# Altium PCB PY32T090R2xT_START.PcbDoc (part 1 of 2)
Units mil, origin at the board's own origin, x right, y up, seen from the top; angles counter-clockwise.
Board outline 1771.65 x 3866.06 mil, 2 copper layers (Top Layer, Bottom Layer), stack 21 mil thick; 137 components, 162 nets, 557 pads, 319 vias.
Unrouted connection lines stored in the file: 5.
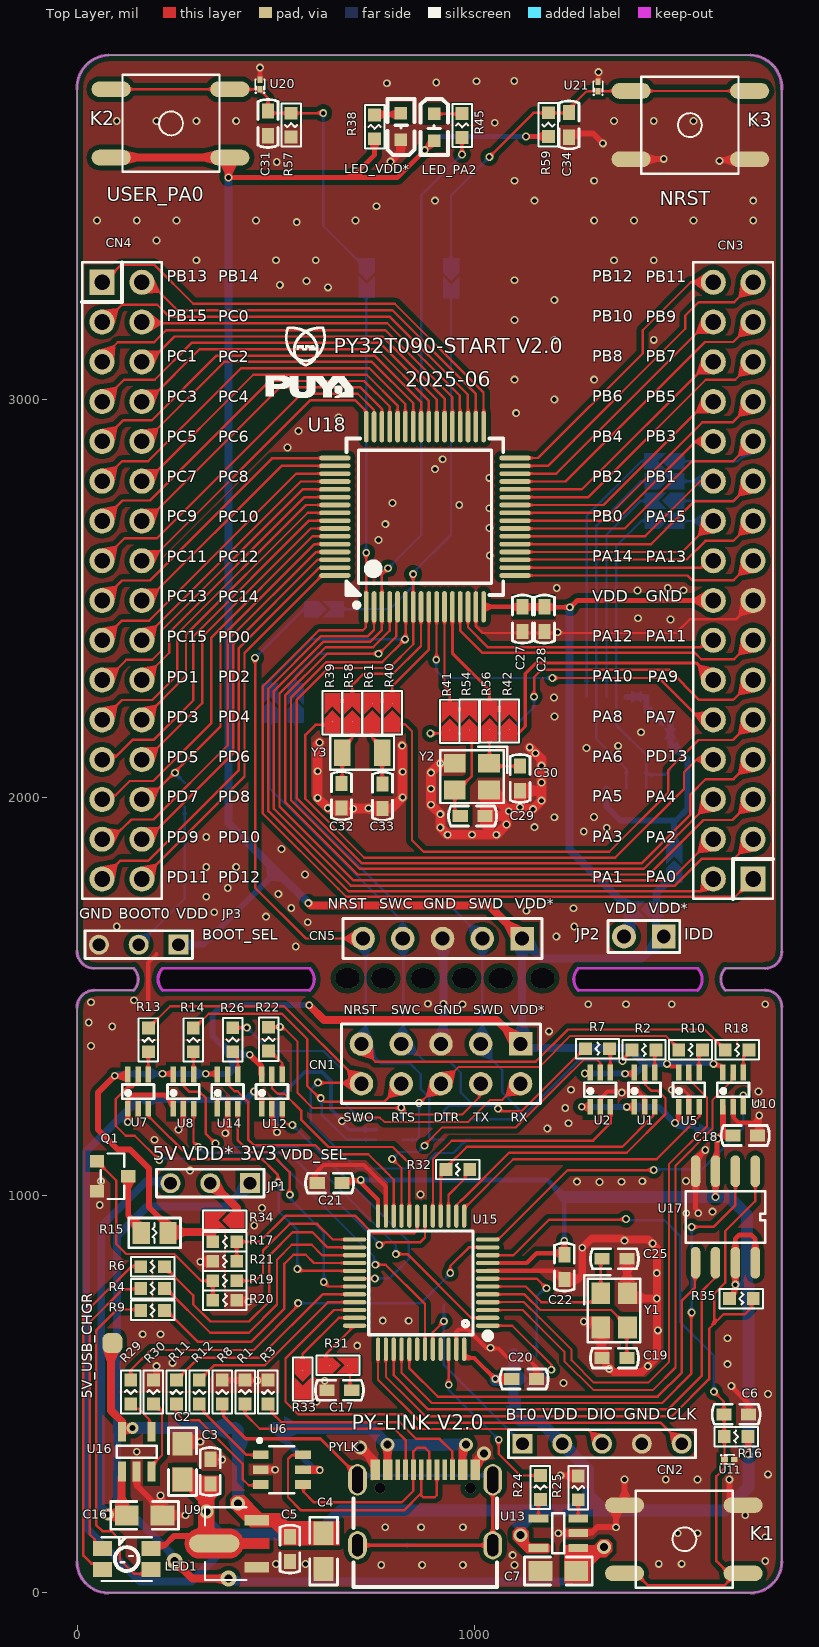
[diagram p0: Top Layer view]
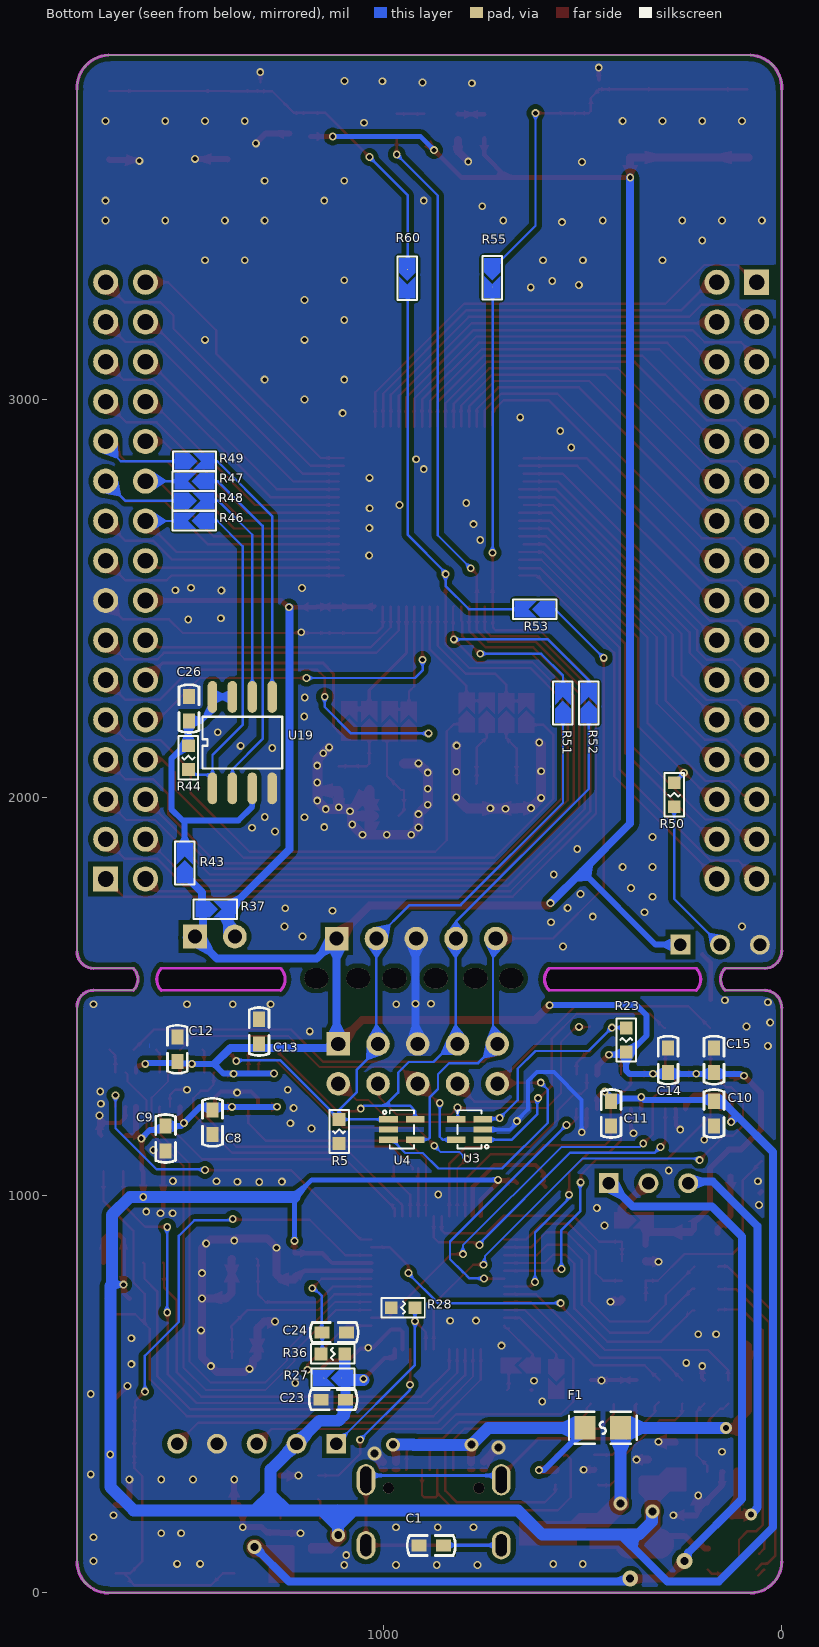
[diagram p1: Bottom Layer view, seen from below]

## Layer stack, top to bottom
Top Solder: solder mask 0.4, Solder Resist, Dk 3.5
Top Layer: signal copper 1.4
Dielectric 2: prepreg 2.8, Composite dielectric, Dk 4.1
Dielectric 1: prepreg 12.6, Composite dielectric, Dk 4.1
Dielectric 3: prepreg 2.8, Composite dielectric, Dk 4.1
Bottom Layer: signal copper 1.4
Bottom Solder: solder mask 0.4, Solder Resist, Dk 3.5

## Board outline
0,78.74 0,1470 cw(c43.75,1471.25) 42.5,1515 142.5,1515 ccw(c115,1542.5) 142.5,1570 42.5,1570 cw(c43.75,1613.75) 0,1615 0,3779.53 cw(c82.64,3783.42) 78.74,3866.06 1692.91,3866.06 cw(c1689.02,3783.43) 1771.65,3779.53 1771.65,1611.65 cw(c1730,1611.65) 1730,1570 1630,1570 ccw(c1657.5,1542.5) 1630,1515 1730,1515 cw(c1730,1473.35) 1771.65,1473.35 1771.65,78.74 cw(c1692.91,78.74) 1692.91,0 78.74,0 cw(c78.74,78.74)
cut-out: 215,1515 cw(c242.5,1542.5) 215,1570 585,1570 cw(c557.5,1542.5) 585,1515 565,1515
cut-out: 1260,1515 cw(c1287.5,1542.5) 1260,1570 1560,1570 cw(c1532.5,1542.5) 1560,1515

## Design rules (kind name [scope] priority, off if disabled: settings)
Clearance polygon [InPolygon] p1: gap=12 ignorepadtopadclearanceinfootprint=TRUE
Clearance [All] p2: gap=8 ignorepadtopadclearanceinfootprint=TRUE
HoleToHoleClearance [All] p1: gap=1 allowstackedmicrovias=TRUE
MinimumSolderMaskSliver [All] p1: minsoldermaskwidth=0
PlaneClearance [All] p1: clearance=8
PlaneConnect [All] p1: planeconnectstyle=Direct reliefexpansion=20 reliefentries=4 reliefconductorwidth=10 reliefairgap=10
PolygonConnect [All] p1: connectstyle=Direct reliefconductorwidth=10 reliefentries=4 polygonreliefangle="90 Angle" airgapwidth=10
RoutingVias [All] p1: holewidth=28 width=50 viastyle="Through Hole" minholewidth=28 minwidth=50 maxholewidth=28 maxwidth=50
SilkToSilkClearance [All] p1: silktosilkclearance=0
SilkToSolderMaskClearance [IsPad] p1: minsilkscreentomaskgap=0 clearancetoexposedcopper=TRUE
SolderMaskExpansion [All] p1: expansion=4 istentingtop=FALSE
UnRoutedNet [All] p1: checkbadconnections=TRUE
Width [All] p1: maxlimit=100 minlimit=5 preferedwidth=8
23 further rules are at their usual default settings.

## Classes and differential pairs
component class PY32T090R2xT_START: 3 C26 C27 C28 C29 C30 C31 C32 C33 C34 CN3 CN4 CN5 JP2 JP3 K2 K3 LED_PA2 LED_VDD* R37 R38 R39 R40 R41 R42 R43 R44 R45 R46 R47 R48 R49 R50 R51 R52 R53 R54 R55 R56 R57 R58 R59 R60 R61 U18 U19 U20 U21 Y2 Y3
component class PY32F403C1xT_LINK: 5V_USB_CHGR C1 C2 C3 C4 C5 C6 C7 C8 C9 C10 C11 C12 C13 C14 C15 C16 C17 C18 C19 C20 C21 C22 C23 C24 C25 CN1 CN2 F1 JP1 K1 LED1 PYLK Q1 R1 R2 R3 R4 R5 R6 R7 R8 R9 R10 R11 R12 R13 R14 R15 R16 R17 R18 R19 R20 R21 R22 R23 R24 R25 R26 R27 R28 R29 R30 R31 R32 R33 R34 R35 R36 U1 U2 U3 U4 U5 U6 U7 U8 U9 U10 U11 U12 U13 U14 U15 U16 U17 Y1

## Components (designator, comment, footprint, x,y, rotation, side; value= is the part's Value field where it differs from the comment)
5V_USB_CHGR "TP_SIN" TP_SIN 89.02,627.93 r90 top
C1 "4.7nF" C0603 881,119 r180 bottom
C2 "10uF" C0805 265,330 r270 top
C3 "100nF" C0603 335,305 r270 top
C4 "10uF" C0805 620,105 r90 top
C5 "100nF" C0603 535,110 r90 top
C6 "100nF" C0603 1657,449 r180 top
C7 "10uF" C0805 1210,55 r0 top
C8 "100nF" C0603 1431,1183 r90 bottom value=104
C9 "100nF" C0603 1548.9,1142.3 r90 bottom value=104
C10 "100nF" C0603 170.2,1204.9 r90 bottom value=104
C11 "100nF" C0603 429,1204.9 r90 bottom value=104
C12 "100nF" C0603 1519.4,1366.6 r270 bottom value=104
C13 "100nF" C0603 1313.8,1411.1 r270 bottom value=104
C14 "100nF" C0603 285.5,1339.2 r270 bottom value=104
C15 "100nF" C0603 170.5,1339.2 r270 bottom value=104
C16 "10uF" C0805 170,195 r180 top
C17 "100nF" C0603 659.59,509.5 r0 top
C18 "100nF" C0603 1680,1150 r180 top value=104
C19 "22pF" C0603 1351.12,590 r0 top
C20 "100nF" C0603 1123.87,537.59 r180 top value=104
C21 "100nF" C0603 635,1030 r0 top value=104
C22 "100nF" C0603 1225.12,819 r90 top value=104
C23 "100nF" C0603 1127.74,485.58 r180 bottom value=104
C24 "100nF" C0603 1125.12,655 r0 bottom value=104
C25 "22pF" C0603 1351.12,840 r180 top
C26 "100nF" C0603 1490.07,2222.92 r270 bottom value=104
C27 "100nF" C0603 1120,2448 r90 top value=104
C28 "1uF" C0603 1175,2448 r90 top
C29 "22pF" C0603 994.4,1953.04 r180 top
C30 "22pF" C0603 1113.83,2047.37 r90 top
C31 "100nF" C0603 480,3694 r90 top
C32 "22pF" C0603 664.8,2003.88 r90 top
C33 "22pF" C0603 767.97,2002.87 r90 top
C34 "100nF" C0603 1237,3690.5 r90 top
CN1 "2X5P" HDR2X5 1115,1380 r180 top
CN2 "CON5" CON5 1120,375 r0 top
CN3 "2X16P 2.54mm" HDR-TH_32P-P2.54-V-M-R2-C16-S2.54-3 1649.59,2544.77 r90 top
CN4 "2X16P 2.54mm" HDR-TH_32P-P2.54-V-M-R2-C16-S2.54-3 113.04,2544.77 r270 top
CN5 "Header 5" HDR1X5 1118.94,1645 r180 top
F1 "JK-SMD0805-050-16V" F0805 450,415 r180 bottom
JP1 "CON3" CON3 435,1030 r180 top
JP2 "CON2" CON2 1475,1650 r180 top
JP3 "CON3" CON3 255,1629.56 r180 top
K1 "TS-KG02S-AT43F" SW-SMD_4P-L6.0-W6.0-P4.50-LS8.5 1527.55,134.7 r180 top
K2 "TS-KG02S-AT43F" SW-SMD_4P-L6.0-W6.0-P4.50-LS8.5 237,3694 r180 top
K3 "TS-KG02S-AT43F" SW-SMD_4P-L6.0-W6.0-P4.50-LS8.5 1540,3690 r0 top
LED1 "MHPA3528RGBCT" LED-ARRAY-SMD_4P-L3.5-W2.8-TL 125,85 r0 top
LED_PA2 "GREEN" 0603_LED 897,3670 r270 top
LED_VDD* "RED" 0603_LED 815,3701 r90 top
PYLK "KH-TYPE-C-16P" USB-C-SMD_KH-TYPE-C-16P 875.2,214.81 r0 top locked
Q1 "2302" SOT23 89.37,1047.4 r90 top value=SI2302
R1 "5.1K" R0603 422.49,504.99 r270 top
R2 "27R" R0603 1425.21,1365 r180 top
R3 "5.1K" R0603 480,505 r90 top
R4 "680R" R0603 190,765 r0 top
R5 "1M" R0603 1113,1160 r90 bottom
R6 "680R" R0603 190,820 r0 top
R7 "27R" R0603 1308.39,1368.1 r180 top
R8 "1M" R0603 365,505 r90 top
R9 "680R" R0603 190,710 r0 top
R10 "27R" R0603 1542.35,1365 r180 top
R11 "27R" R0603 250,505 r90 top
R12 "27R" R0603 307.5,505 r90 top
R13 "27R" R0603 179.66,1390.08 r90 top
R14 "27R" R0603 292.3,1390.1 r90 top
R15 "100R" R0805 195,905 r0 top
R16 "10K" R0603 1657,393 r0 top
R17 "20K" R0603 371.52,882.61 r180 top
R18 "27R" R0603 1659.49,1365 r180 top
R19 "100R" R0603 371.53,784.78 r0 top
R20 "100K" R0603 371.52,735.88 r180 top
R21 "10K" R0603 371.53,833.69 r0 top
R22 "27R" R0603 481.63,1392.11 r90 top
R23 "4.7K" R0603 391,1390 r270 bottom
R24 "4.7K" R0603 1165,265 r270 top
R25 "16K" R0603 1260,264 r270 top
R26 "27R" R0603 391.2,1390.7 r90 top
R27 "0R" JP2_SMD 1128,540 r180 bottom
R28 "10K" R0603 952,717.08 r0 bottom
R29 "4.7K" R0603 135,505 r270 top
R30 "16K" R0603 192,505 r270 top
R31 "0R" JP2_SMD 656.21,571.75 r180 top
R32 "680R" R0603 957.46,1064.37 r0 top
R33 "0R" JP2_SMD 566.96,537.4 r90 top
R34 "0R" JP2_SMD 371,937 r0 top
R35 "100K" R0603 1670,740 r180 top
R36 "10K" R0603 1128.6,600.62 r180 bottom
R37 "0R" JP2_SMD 1423.75,1718.35 r0 bottom
R38 "680R" R0603 748,3685.5 r270 top
R39 "0R" JP2_SMD 642.19,2212.17 r270 top
R40 "0R" JP2_SMD 792,2213 r270 top
R41 "0R" JP2_SMD 937.26,2190.77 r270 top
R42 "0R" JP2_SMD 1087,2192 r270 top
R43 "0R/NC" JP2_SMD 1501,1835 r270 bottom
R44 "100K" R0603 1491.66,2099.84 r90 bottom
R45 "680R" R0603 968,3689 r270 top
R46 "0R/NC" JP2_SMD 1477,2695.26 r180 bottom
R47 "0R/NC" JP2_SMD 1476.59,2794.33 r180 bottom
R48 "0R/NC" JP2_SMD 1477,2745.33 r0 bottom
R49 "0R/NC" JP2_SMD 1476.22,2844.64 r0 bottom
R50 "10K" R0603 270.51,2006.45 r90 bottom
R51 "0R" JP2_SMD 550,2237 r270 bottom
R52 "0R" JP2_SMD 485,2237 r270 bottom
R53 "0R" JP2_SMD 621,2473 r180 bottom
R54 "0R" JP2_SMD 985.95,2191.17 r270 top
R55 "0R" JP2_SMD 728,3306 r90 bottom
R56 "0R" JP2_SMD 1037,2192 r270 top
R57 "1.5K" R0603 538,3690 r90 top
R58 "0R" JP2_SMD 692.33,2212.17 r270 top
R59 "10K" R0603 1185,3691 r90 top
R60 "0R" JP2_SMD 941,3305 r90 bottom
R61 "0R" JP2_SMD 742.01,2212.69 r270 top
U1 "74LVC1T45DW" SOT363 1426.64,1265 r0 top
U2 "74LVC1T45DW" SOT363 1315.21,1265 r0 top
U3 "ESDALC6V1W5" ESD_SOT323-5L 785,1165 r90 bottom
U4 "ESDALC6V1W5" ESD_SOT323-5L 955,1165 r270 bottom
U5 "74LVC1T45DW" SOT363 1538.06,1265 r0 top locked
U6 "USBLC6-2SC6" SOT23-6 515,310 r90 top
U7 "74LVC1T45DW" SOT363 153.55,1260 r0 top locked
U8 "74LVC1T45DW" SOT363 267.26,1260 r0 top
U9 "LM1117F-3.3" SOT-89-3_L4.5-W2.5-P1.50-LS4.2-BR 398.39,124.01 r0 top
U10 "74LVC1T45DW" SOT363 1649.49,1265 r0 top
U11 "ESDALC6V1-1U2" ESD_ST0201 1640,335 r0 top
U12 "74LVC1T45DW" SOT363 490.12,1260 r0 top
U13 "MT9700" SOT23-5 1210,150 r90 top
U14 "74LVC1T45DW" SOT363 378.69,1260 r0 top
U15 "PY32F403C1xT" LQFP-48_L7.0-W7.0-P0.50-LS9.0-BL 865,780 r90 top locked
U16 "MT9700" SOT23-5 150,355 r0 top
U17 "P25Q64SH" SOP-8P 1630,945 r180 top value=SST25VF020B
U18 "PY32T090R2xT7" LQFP-64_L10.0-W10.0-P0.50-LS12.0-BL 874.65,2705.31 r0 top locked
U19 "P25Q64SH" SOP-8P 1356.15,2137.48 r180 bottom locked value=SST25VF020B
U20 "ESDALC6V1-1U2" ESD_ST0201 460,3792 r90 top
U21 "ESDALC6V1-1U2" ESD_ST0201 1310,3787 r90 top
Y1 "24MHz" CRYSTAL-SMD_4P-L3.2-W2.5-BL 1350.12,710 r270 top
Y2 "24MHz" CRYSTAL-SMD_4P-L3.2-W2.5-BL 992.87,2051.95 r180 top
Y3 "32.768KHz" CRYSTAL-SMD_L3.2-W1.5-1 716.89,2111.6 r180 top value=32.768kHz

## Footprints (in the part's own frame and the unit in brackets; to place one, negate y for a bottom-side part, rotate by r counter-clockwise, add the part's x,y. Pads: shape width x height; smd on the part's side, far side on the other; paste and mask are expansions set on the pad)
0603_LED [mil]
  rect 31.5x31.5 smd: 1(19,1) 2(-48,1)
  silkscreen extent -86,-33 55,35
C0603 [mil]
  rect 38x30 smd: 1(-31,0) 2(31,0)
  silkscreen extent -60,-25 60,25
C0805 [mil]
  rect 60x50 smd: 1(-45,0) 2(45,0)
  silkscreen extent -85,-35 85,35
CON2 [mil]
  rect 60x60 hole 35: 1(0,0)
  round 60 hole 35: 2(100,0)
  silkscreen extent -40,-40 140,40
CON3 [mil]
  rect 50x50 hole 32: 1(0,0)
  round 50 hole 32: 2(100,0) 3(200,0)
  silkscreen extent -35,-35 235,35
CON5 [mil]
  rect 50x50 hole 32: 1(0,0)
  round 50 hole 32: 2(100,0) 3(200,0) 4(300,0) 5(400,0)
  silkscreen extent -35,-35 435,35
CRYSTAL-SMD_4P-L3.2-W2.5-BL [mm]
  rect 1.4x1.2 smd: 1(-1.1,-0.85) 2(1.1,-0.85) 3(1.1,0.85) 4(-1.1,0.85)
  silkscreen extent -2.26,-1.91 2.03,1.68
CRYSTAL-SMD_L3.2-W1.5-1 [mm]
  rect 1.05x1.7 smd: 1(-1.275,0) 2(1.275,0)
  silkscreen extent -2.03,-1.08 2.03,1.08
ESD_SOT323-5L [mm]
  rect 0.4x1.2 smd mask+0.05: 1(-0.65,-0.85) 2(0,-0.85) 3(0.65,-0.85) 4(0.65,0.85) 5(-0.65,0.85)
  silkscreen extent -1.23,-1.21 1.23,0.77, body extent -1.15,-1.05 1.15,1.05, height 1.1
ESD_ST0201 [mm]
  rect 0.425x0.33 smd mask+0.05: 1(-0.312,0) 2(0.312,0)
  silkscreen extent -0.55,-0.3 0.33,0.3, body extent -0.34,-0.18 0.34,0.18, height 0.34
F0805 [mm]
  rect 1.335x1.5 smd paste-100 mask+0.051: 1(-1.142,0) 2(1.142,0)
  silkscreen extent -2.16,-1.02 2.16,1.02
HDR1X5 [mm] "Connector; Header; 5 Position"
  rect 1.5x1.5 hole 0.9: 1(0,0)
  round 1.5 hole 0.9: 2(2.54,0) 3(5.08,0) 4(7.62,0) 5(10.16,0)
  silkscreen extent -1.27,-1.27 11.43,1.27
HDR2X5 [mm] "Connector; Header; 4x2 Position"
  rect 1.5x1.5 hole 0.9: 1(0,0)
  round 1.5 hole 0.9: 2(0,2.54) 3(2.54,0) 4(2.54,2.54) 5(5.08,0) 6(5.08,2.54) 7(7.62,0) 8(7.62,2.54) 9(10.16,0) 10(10.16,2.54)
  silkscreen extent -1.27,-1.27 11.43,3.81
HDR-TH_32P-P2.54-V-M-R2-C16-S2.54-3 [mm]
  rect 1.6x1.6 hole 1: 1(-19.05,-1.27)
  round 1.6 hole 1: 2(-19.05,1.27) 3(-16.51,-1.27) 4(-16.51,1.27) 5(-13.97,-1.27) 6(-13.97,1.27) 7(-11.43,-1.27) 8(-11.43,1.27) 9(-8.89,-1.27) 10(-8.89,1.27) 11(-6.35,-1.27) 12(-6.35,1.27) 13(-3.81,-1.27) 14(-3.81,1.27) 15(-1.27,-1.27) 16(-1.27,1.27) 17(1.27,-1.27) 18(1.27,1.27) 19(3.81,-1.27) 20(3.81,1.27) 21(6.35,-1.27) 22(6.35,1.27) 23(8.89,-1.27) 24(8.89,1.27) 25(11.43,-1.27) 26(11.43,1.27) 27(13.97,-1.27) 28(13.97,1.27) 29(16.51,-1.27) 30(16.51,1.27) 31(19.05,-1.27) 32(19.05,1.27)
  silkscreen extent -20.32,-2.54 20.32,2.54
JP2_SMD [mil]
  round 1 smd: 1(21.75,0) 2(-23.03,0.03)
  Top Layer region: -49.77,20.03 -49.77,20.03 3.72,20.03 -16.28,0.03 3.72,-19.98 -49.78,-19.98 -49.78,-19.98
  Top Layer region: -6.25,0 13.75,20 49.75,20 49.75,-20 49.75,-20 13.75,-20
  silkscreen extent -55,-25 54,25
LED-ARRAY-SMD_4P-L3.5-W2.8-TL [mm]
  rect 1.2x0.95 smd: 1(1.55,0.665) 2(1.55,-0.665) 3(-1.55,-0.665) 4(-1.55,0.665)
  silkscreen extent -1.6,-1.4 1.6,1.4
LQFP-48_L7.0-W7.0-P0.50-LS9.0-BL [mm]
  oval 0.27x1.5 smd mask+0.05: 1(-2.75,-4.25) 2(-2.25,-4.25) 3(-1.75,-4.25) 4(-1.25,-4.25) 5(-0.75,-4.25) 6(-0.25,-4.25) 7(0.25,-4.25) 8(0.75,-4.25) 9(1.25,-4.25) 10(1.75,-4.25) 11(2.25,-4.25) 12(2.75,-4.25) 25(2.75,4.25) 26(2.25,4.25) 27(1.75,4.25) 28(1.25,4.25) 29(0.75,4.25) 30(0.25,4.25) 31(-0.25,4.25) 32(-0.75,4.25) 33(-1.25,4.25) 34(-1.75,4.25) 35(-2.25,4.25) 36(-2.75,4.25)
  oval 1.5x0.27 smd mask+0.05: 13(4.25,-2.75) 14(4.25,-2.25) 15(4.25,-1.75) 16(4.25,-1.25) 17(4.25,-0.75) 18(4.25,-0.25) 19(4.25,0.25) 20(4.25,0.75) 21(4.25,1.25) 22(4.25,1.75) 23(4.25,2.25) 24(4.25,2.75) 37(-4.25,2.75) 38(-4.25,2.25) 39(-4.25,1.75) 40(-4.25,1.25) 41(-4.25,0.75) 42(-4.25,0.25) 43(-4.25,-0.25) 44(-4.25,-0.75) 45(-4.25,-1.25) 46(-4.25,-1.75) 47(-4.25,-2.25) 48(-4.25,-2.75)
  silkscreen extent -3.59,-4.46 3.3,3.34
LQFP-64_L10.0-W10.0-P0.50-LS12.0-BL [mm]
  oval 0.3x2 smd: 1(-3.75,-5.75) 2(-3.25,-5.75) 3(-2.75,-5.75) 4(-2.25,-5.75) 5(-1.75,-5.75) 6(-1.25,-5.75) 7(-0.75,-5.75) 8(-0.25,-5.75) 9(0.25,-5.75) 10(0.75,-5.75) 11(1.25,-5.75) 12(1.75,-5.75) 13(2.25,-5.75) 14(2.75,-5.75) 15(3.25,-5.75) 16(3.75,-5.75) 33(3.75,5.75) 34(3.25,5.75) 35(2.75,5.75) 36(2.25,5.75) 37(1.75,5.75) 38(1.25,5.75) 39(0.75,5.75) 40(0.25,5.75) 41(-0.25,5.75) 42(-0.75,5.75) 43(-1.25,5.75) 44(-1.75,5.75) 45(-2.25,5.75) 46(-2.75,5.75) 47(-3.25,5.75) 48(-3.75,5.75)
  oval 2x0.3 smd: 17(5.75,-3.75) 18(5.75,-3.25) 19(5.75,-2.75) 20(5.75,-2.25) 21(5.75,-1.75) 22(5.75,-1.25) 23(5.75,-0.75) 24(5.75,-0.25) 25(5.75,0.25) 26(5.75,0.75) 27(5.75,1.25) 28(5.75,1.75) 29(5.75,2.25) 30(5.75,2.75) 31(5.75,3.25) 32(5.75,3.75) 49(-5.75,3.75) 50(-5.75,3.25) 51(-5.75,2.75) 52(-5.75,2.25) 53(-5.75,1.75) 54(-5.75,1.25) 55(-5.75,0.75) 56(-5.75,0.25) 57(-5.75,-0.25) 58(-5.75,-0.75) 59(-5.75,-1.25) 60(-5.75,-1.75) 61(-5.75,-2.25) 62(-5.75,-2.75) 63(-5.75,-3.25) 64(-5.75,-3.75)
  silkscreen extent -5,-5.79 5,5
R0603 [mil]
  rect 32x32 smd: 1(-30,0) 2(30,0)
  silkscreen extent -55,-24 54,25
R0805 [mm]
  rect 1.1x1.4 smd: 1(-0.85,0) 2(0.85,0)
  silkscreen extent -1.65,-0.95 1.65,0.95
SOP-8P [mil]
  oval 24x80 smd: 1(-75,-115) 2(-25,-115) 3(25,-115) 4(75,-115) 5(75,115) 6(25,115) 7(-25,115) 8(-75,115)
  silkscreen extent -100,-65 100,65
SOT23 [mm]
  rect 0.8x0.9 smd: 1(0.95,1) 2(-0.95,1) 3(0,-1)
  silkscreen extent -1.45,-0.75 1.45,0.75
SOT23-5 [mil]
  rect 20x50 smd: 1(-37.5,-50) 2(0,-50) 3(37.5,-50) 4(37.5,50) 5(-37.5,50)
  silkscreen extent -50,-15 50,15
SOT23-6 [mm]
  rect 0.55x1 smd: 1(0.95,1.35) 2(0,1.35) 3(-0.95,1.35) 4(-0.95,-1.35) 5(0,-1.35) 6(0.95,-1.35)
  silkscreen extent -1.5,-0.8 1.96,1.52
SOT363 [mm]
  rect 0.35x1 smd: 1(-0.65,-1.1) 2(0,-1.1) 3(0.65,-1.1) 4(0.65,1.1) 5(0,1.1) 6(-0.65,1.1)
  silkscreen extent -1.02,-0.45 1.02,0.45, body extent -1,-1.1 1,1.16, height 1
SOT-89-3_L4.5-W2.5-P1.50-LS4.2-BR [mm]
  rect 1.575x0.672 smd: 1(1.356,-1.5) 3(1.356,1.5)
  oval 3.226x1.14 smd: 2(-1.356,0)
  Top Layer region: -2.283,0.95 -0.429,0.95 -0.384,0.949 -0.34,0.946 -0.296,0.94 -0.252,0.933 -0.208,0.924 -0.165,0.912 -0.123,0.899 -0.081,0.884 -0.04,0.866 0,0.847 0.04,0.826 0.078,0.803 0.115,0.779 0.151,0.752 0.185,0.724 0.219,0.695 0.251,0.664 0.281,0.631 0.31,0.597 0.337,0.562 0.362,0.525 0.386,0.488 0.408,0.449 0.428,0.409 0.447,0.33 2.144,0.33 2.144,-0.33 0.447,-0.33 0.428,-0.409 0.408,-0.449 0.386,-0.488 0.362,-0.526 0.337,-0.562 0.31,-0.597 0.281,-0.631 0.251,-0.664 0.219,-0.695 0.185,-0.725 0.151,-0.753 0.115,-0.779 0.078,-0.804 0.04,-0.827 0,-0.848 -0.04,-0.867 -0.081,-0.884 -0.123,-0.899 -0.165,-0.913 -0.208,-0.924 -0.252,-0.934 -0.296,-0.941 -0.34,-0.946 -0.384,-0.949 -0.429,-0.95 -2.283,-0.95 -2.328,-0.949 -2.372,-0.946 -2.416,-0.941 -2.46,-0.934 -2.504,-0.924 -2.547,-0.913 -2.589,-0.899 -2.631,-0.884 -2.672,-0.867 -2.713,-0.848 -2.752,-0.827 -2.79,-0.804 -2.827,-0.779 -2.863,-0.753 -2.898,-0.725 -2.931,-0.695 -2.963,-0.664 -2.993,-0.631 -3.022,-0.597 -3.049,-0.562 -3.075,-0.526 -3.098,-0.488 -3.12,-0.449 -3.141,-0.409 -3.159,-0.369 -3.175,-0.327 -3.189,-0.285 -3.202,-0.242 -3.212,-0.199 -3.22,-0.155 -3.227,-0.111 -3.231,-0.067 -3.233,-0.022 -3.233,0.022 -3.231,0.067 -3.227,0.111 -3.22,0.155 -3.212,0.199 -3.202,0.242 -3.189,0.285 -3.175,0.327 -3.159,0.369 -3.141,0.409 -3.12,0.449 -3.098,0.488 -3.075,0.525 -3.049,0.562 -3.022,0.597 -2.993,0.631 -2.963,0.664 -2.931,0.695 -2.898,0.724 -2.863,0.752 -2.827,0.779 -2.79,0.803 -2.752,0.826 -2.713,0.847 -2.672,0.866 -2.631,0.884 -2.589,0.899 -2.547,0.912 -2.504,0.924 -2.46,0.933 -2.416,0.94 -2.372,0.946 -2.328,0.949 -2.283,0.95
  silkscreen extent -1.95,-2.33 0.7,2.33
SW-SMD_4P-L6.0-W6.0-P4.50-LS8.5 [mm]
  oval 2.5x1 smd: 1(-3.734,2.177) 2(3.835,2.177) 3(-3.734,-2.184) 4(3.835,-2.184)
  silkscreen extent -3.08,-3.1 3.12,3.09, body extent -4.48,-3 4.52,3, height 8.95
TP_SIN [mil]
  rrect60% 50x50 smd: 1(0,0)
USB-C-SMD_KH-TYPE-C-16P [mm]
  oval 1.2x2 hole 0.7 slot 1.7 at 90 deg: 1(-4.32,1.765) 2(4.32,1.765)
  oval 1.2x1.8 hole 0.7 slot 1.4 at 90 deg: 3(-4.32,-2.415) 4(4.32,-2.415)
  rect 0.3x1.3 smd: A1(-3.35,2.415) A4(-2.55,2.415) A5(-1.25,2.415) A6(-0.25,2.415) A7(0.25,2.415) A8(1.25,2.415) A9(2.55,2.415) A12(3.35,2.415) B1(3.05,2.415) B4(2.25,2.415) B5(1.75,2.415) B6(0.75,2.415) B7(-0.75,2.415) B8(-1.75,2.415) B9(-2.25,2.415) B12(-3.05,2.415)
  round 0.7 hole 0.7 unplated: ""(-2.89,1.235) ""(2.89,1.235)
  silkscreen extent -4.57,-5.08 4.57,0.57

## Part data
C1 C3 C5 C6 C17 C19 C25 C29 C30 C31 C32 C33 C34: library part C0603
C2 C4 C7 C16 C28: library part C0805
C8 C9 C10 C11 C12 C13 C14 C15 C18 C20 C21 C22 C23 C24 C26 C27: library part 贴片高压陶瓷电容, "Capacitor (Semiconductor SIM Model)"
CN1: Color=黑色, Current Rating (Max)=-, JLCPCB Part Class="Extended Part", LCSC Part Name="间距:2.54mm 2x5P 直插 方针", Manufacturer=XFCN(兴飞), Manufacturer Part=PZ254V-12-10P, Operating Temperature Range=-40℃~+105℃
CN3 CN4: Color=黑色, Current Rating (Max)=3A, JLCPCB Part Class="Extended Part", LCSC Part Name="2x16P 间距:2.54mm 方针", Manufacturer="XKB Connection(中国星坤)", Manufacturer Part=X6522WV-2x16H-C60D30-E80, Operating Temperature Range=-40℃~+105℃, Soldering Temperature(Max)=260℃, Voltage Rating (Max)=250V
CN5: "Header, 5-Pin"
F1: Current - Max=100A, Hold Current=500mA, JLCPCB Part Class="Extended Part", LCSC Part Name="6V 0.5A 贴片自恢复", Manufacturer=JK(金科), Operating Temperature=-40℃~+85℃, Power Dissipation=600mW, Resistance - Initial (Ri) (Min)=150mΩ, Resistance - Post Trip (R1) (Max)=850mΩ, Trip Current=1A, Voltage - Max=6V
JP2: library part CON2_DIP
K1 K2 K3: Actuator/Cap Color=黑色, Contact Current=50mA, Insulation Resistance=100MΩ, JLCPCB Part Class=扩展库, LCSC Part Name="6*6*4.3mm 立贴 轻触开关", Manufacturer=HANBO(汉博), Operating Force=250gf, Voltage Rating (DC)=12V
LED1: JLCPCB Part Class=扩展库, LCSC Part Name=RGB三色, Manufacturer=MEIHUA(美华)
LED_PA2 LED_VDD*: library part PDI-E803_Dup1
PYLK: BOM_JLCPCB Part Class="Extended Part", BOM_Manufacturer="Shenzhen Kinghelm Elec"
Q1: library part "MOSFET N", "MOSFET N"
R1 R2 R3 R4 R5 R6 R7 R8 R9 R10 R11 R12 R13 R14 R16 R17 R18 R19 R20 R21 R22 R23 R24 R26 R27 R28 R29 R31 R32 R33 R34 R35 R36 R37 R38 R39 R40 R41 R42 R43 R44 R45 R46 R47 R48 R49 R50 R51 R52 R53 R54 R55 R56 R57 R58 R59 R60 R61: library part R0603
R15: library part R0805
R25 R30: library part R0603_7, "0603WAF1602T5E 16KΩ(1602) ±1%"
U3 U4: "Dual Transil array for ESD protection", Manufacturer=STMICROELECTRONICS
U11 U20 U21: "ESD protection 6V1", Manufacturer=STMICROELECTRONICS
U15: "LQFP48", BOM_Manufacturer=PUYA(普冉)
U17 U19: library part SST25VF010, "SST25VF010"
U18: library part PY32F072x
Y1 Y2: library part ABM8AIG-24.000MHZ-82Z-T, "±20ppm , 12.5pF , T_use: -40°C~125°C", Equivalent Series Resistance (ESR)=50Ω, External load capacitor=8pF, Frequency Stability(Full temperature range)=±50ppm, JLCPCB Part Class="Extended Part", LCSC Part Name="24MHz ±20ppm 8pF", Manufacturer=ABRACON, Normal temperature Frequency Tolerance=±20ppm, Operating Temperature=-40℃~+125℃
Y3: library part XKXGI-SUA-32.768K, "±20ppm , 12.5pF , T_use: -40°C~125°C", External load capacitor=12.5pF, Frequency Stability(Full temperature range)=±30ppm, JLCPCB Part Class="Extended Part", LCSC Part Name="32.768kHz ±20ppm 12.5pF YST310S", Manufacturer=YXC(扬兴晶振), Normal temperature Frequency Tolerance=±20ppm, Operating Temperature=-40℃~+85℃

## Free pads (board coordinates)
  oval 60x50 hole 50 slot 60 at 0 deg unplated: 1(680,1545) 1(770,1545) 1(870,1545) 1(973.55,1545) 1(1065,1545) 1(1170,1545)

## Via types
v1: diameter 19.68, hole 11.81, Top Layer to Bottom Layer, 161 vias
v2: diameter 19.68, hole 11.81, Top Layer to Bottom Layer, tented both sides, 146 vias
v3: diameter 35, hole 20, Top Layer to Bottom Layer, tented both sides, 8 vias
v4: diameter 30, hole 15, Top Layer to Bottom Layer, tented both sides, 2 vias
v5: diameter 40, hole 20, Top Layer to Bottom Layer, tented both sides, 2 vias

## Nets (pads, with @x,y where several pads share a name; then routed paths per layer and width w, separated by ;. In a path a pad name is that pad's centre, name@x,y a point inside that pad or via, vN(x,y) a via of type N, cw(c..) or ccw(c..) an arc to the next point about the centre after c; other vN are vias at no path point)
3.3V_OUT_EN: R24.1 U15.46 | length 443
  Top Layer w6: U15.46@933.9,612.68 934.26,612.32 934.26,523.74 v2(934.62,523.38) ; v2(1060,385) 1060,349.4 1114.4,295 R24.1@1165,295
  Bottom Layer w6: v2(934.62,523.38) 934.62,510.38 v2(1060,385)
3V3_PYLK: C2.2 C3.2 C8.2 C9.2 C10.2 C11.2 C18.2 C20.2 C21.2 C22.2 C23.2 CN2.2 LED1.1 R16.2 R27.1 R35.2 R36.2 U1.1 U2.1 U5.1 U7.1 U8.1 U9.2 U10.1 U12.1 U13.5 U14.1 U15.9 U15.24 U15.48 U17.3 U17.7 U17.8 | length 7902.7
  Top Layer w10: v2(445.16,1260.63) 449.42,1260.63 464.53,1245.52 U12.1@464.53,1216.69 ; C21.2@666,1030 C21.2@670.66,1034.66 ; C22.2@1225,854.12 v2(1225,885) ; v2(1688,348) R16.2@1688,393
  Top Layer w11: v2@710,1035 756.73,988.27 U15.24@756.73,947.32 ; U15.48@973.27,612.68 973.27,590.61 973.45,590.42 998.23,590.42 1053.65,535 v2@1055.12,535 ; U15.9@1032.32,829.21 1130.39,829.21 1155.3,854.12 C22.2@1225,854.12
  Top Layer w12: v1(127.35,1183.66) 127.96,1184.27 U7.1@127.96,1216.69 127.96,1237.87 141.96,1251.88 219.81,1251.88 241.67,1230.01 U8.1@241.67,1216.69 ; U14.1@353.1,1216.69 353.99,1217.58 353.12,1218.46 v2(353.12,1246.39) ; C21.2@670.66,1034.66 671.99,1035.99 710.99,1035.99 v2(713.28,1038.28) ; v2(1268.73,1222.03) 1269.06,1221.69 U2.1@1289.62,1221.69 ; v2(1382,1221.9) 1382.21,1221.69 U1.1@1401.05,1221.69 ; v1(1503.01,1181.02) 1512.47,1190.48 U5.1@1512.47,1221.69 1511.58,1220.8 U5.1@1511.8,1220.58 ; v2(1605,995) U17.3@1605,1060 1609.01,1064.01 1609.01,1141.25 v2(1609.87,1142.11) ; 1617.76,1150 C18.2@1649,1150 ; R35.2@1640,740 1655,755 v2(1655,775) U17.7@1655,830 1655,890 1665,900 1695,900 1705,890 U17.8@1705,830
  Top Layer w15: LED1.1@186.02,111.18 193.48,111.18 193.48,111.66 202.14,120.32 221.03,120.32 244.3,143.59 U9.2@313.8,143.59 ; v2(1609.87,1142.11) 1617.76,1150 1623.9,1156.14 U10.1@1623.9,1221.69
  Top Layer w20: v2@1054.87,537.59 C20.2@1092.87,537.59
  Bottom Layer w12: v2(713.28,1038.28) 1181.72,1038.28 1225,995 ; v2(1225,885) 1225,990 ; v2(1655,775) 1683.73,775 1684.65,775
  Bottom Layer w15: C10.2@170.2,1235.9 173.64,1239.34 346.07,1239.34 v2(353.12,1246.39) 356.92,1242.6 422.3,1242.6 C11.2@429,1235.9 429,1244.47 v2(445.16,1260.63) v2@443.56,1262.22 ; v2(1268.73,1222.03) 1462,1222.03 v1(1503.01,1181.02) 1510.73,1173.3 C9.2@1548.9,1173.3 ; C9.2@1558.32,1163.88 1588.1,1163.88 v2(1609.87,1142.11)
  Bottom Layer w20: v1(127.35,1183.66) 112.87,1198.15 111.65,1198.15 ; C10.2@170.2,1244.2 157.7,1244.2 111.65,1198.15 ; 405.3,146.25 287.88,28.84 158.16,28.84 22,165 22,1108.5 111.65,1198.15 ; v2(1051.39,538) 1091.65,538 1096.74,538
  Bottom Layer w25: C23.2@1096.74,485.58 1096.74,538
  Bottom Layer w30: v3(325,205) 325.96,204.04 325.96,179.91 359.61,146.25 405.3,146.25 602.14,146.25 663.2,207.32 1115.96,207.32 ; v2@1051.65,535.41 1091.65,535.41 1091.65,538 ; C23.2@1096.74,485.58 1100.74,485.58 1100.74,446.28 1114.31,432.7 1162.3,432.7 CN2.2@1220,375 1285,310 1285,207.32 ; R36.2@1098.6,600.62 1098.6,547.65 R27.1@1106.25,540 ; v3(1115,145) 1115.96,145.96 1115.96,207.32 ; 1225,995 v2(1605,995) 1638.96,995 1683.73,950.23 1683.73,775 ; 1684.65,775 1688,771.65 v2(1688,348) 1688,266.15 1629.17,207.32 1285,207.32 ; 1115.96,207.32 1285,207.32
3V3_USB_PYLK: C7.2 JP1.1 U13.1 | length 2404.2
  Top Layer w20: v5@245.8,80 290.03,35.77 v5(380.96,35.77)
  Bottom Layer w20: v5(245,80) 245,85.41 235.27,95.14 235.27,100.98 100.1,236.16 100.1,895.86 175.6,971.36 374.6,971.36 418.24,1015 420,1015 433.24,1028.24 JP1.1@433.24,1030 ; v5(380.96,35.77) 387.82,28.91 1238.91,28.91 v3(1325,115) v3@1326.78,113.22
5V_OUT_EN: R29.1 U15.11 | length 1065.3
  Top Layer w6: R29.1@135,535 135,560 185.65,610.65 444.42,610.65 555.92,722.16 v2(555.92,728.42) ; v2(938.27,804.07) 938.27,821.87 984.98,868.58 U15.11@1032.32,868.58
  Bottom Layer w6: v2(555.92,728.42) 864.41,728.42 938.27,802.29 v2(938.27,804.07)
5V_USB_CHGR: 5V_USB_CHGR.1 C4.2 C5.2 F1.2 U9.3 U16.5 | length 712.1
  Top Layer w20: 5V_USB_CHGR.1@90,625 85.21,620.21 85.21,458.5 112.5,431.21 U16.5@112.5,405 ; U16.5@112.5,413.09 138.09,413.09 v4(140,415)
  Bottom Layer w30: v4(140,415) 397.38,415 405,407.38 v3(405,225)
5V_USB_PYLK: C16.2 JP1.3 U16.1 | length 1109.9
  Top Layer w20: v4(77.39,196.82) 78.3,195.91 124.09,195.91 C16.2@125,195 ; U16.1@112.5,304.69 112.5,290 112.19,289.69 112.19,210 C16.2@125,210
  Bottom Layer w20: v4(77.39,196.82) 74.92,197.32 71.21,201.03 69.81,202.43 60.92,215.77 60.92,921.89 172.85,1033.82 231.18,1033.82 JP1.3@235,1030
AD_TVDD: R17.1 R21.2 U15.19 | length 586.3
  Top Layer w6: R21.2@401.52,833.7 R17.1@401.52,882.61 458.79,882.61 523.97,947.79 699.66,947.79 743.59,903.86 846.86,903.86 855.16,912.17 U15.19@855.16,947.32
BOOT0: CN4.28 R50.2 U18.60 | length 916.8
  Top Layer w6: CN4.28@163.04,1994.77 177.58,1994.77 245.32,2062.51 360.65,2177.84 360.65,2400.37 596.76,2636.47 U18.60@648.34,2636.47
  Bottom Layer w6: v1(246.11,2061.73) 246.11,2060.85 R50.2@270.51,2036.45
DIR_RESET: U10.5 U15.3 | length 1394.4
  Top Layer w5: U15.3@1032.32,711.1 1120.66,711.1 1160.03,671.73 1225.22,606.55 1225.22,582.77 1297.78,510.22 1448.12,510.22 1504.53,566.63 1504.53,1074.04 1596.97,1166.47 1596.97,1238.45 1645.1,1286.59 1645.1,1303.92 U10.5@1649.49,1308.31
DIR_RTCK_DTR: U5.5 U15.4 | length 1362.6
  Top Layer w5: U15.4@1032.32,730.79 1123.69,730.79 1163.06,691.42 1243.43,611.05 1243.43,584.49 1299.09,528.83 1435.95,528.83 1488.53,581.41 1488.53,1078.32 1583.97,1173.76 1583.97,1245.09 1542.45,1286.6 1542.45,1303.92 U5.5@1538.06,1308.31
DIR_TCK_SWCLK: U2.5 U15.21 | length 808
  Top Layer w5: v2(792.12,1090.67) 815.79,1067 U15.21@815.79,947.32 ; v1(873.49,1124.13) 873.49,1125.57 917.33,1169.41 1102.34,1169.41 1216.71,1283.79 1273.38,1340.46 1307.19,1340.46 1315.21,1332.43 U2.5@1315.21,1308.31
  Bottom Layer w5: v2(792.12,1090.67) 809.61,1108.16 857.52,1108.16 v1(873.49,1124.13)
DIR_TDI_VCP_TX: U12.5 U15.20 | length 603.7
  Top Layer w6: U12.5@490.12,1303.31 490.12,1268.77 503.92,1254.98 520.97,1254.98 563.25,1212.7 563.25,1189.92 632.11,1121.06 793.64,1121.06 835.47,1079.24 U15.20@835.47,947.32
DIR_TDO_SWO: U7.5 U15.43 | length 1250.3
  Top Layer w6: U7.5@153.55,1303.31 153.55,1284.73 140.19,1271.38 127.22,1271.38 97.4,1241.56 97.4,1174.28 122.48,1149.2 145.25,1149.2 v1(206.55,1087.9) ; v2(750,825) 775.69,825 874.84,725.85 U15.43@874.84,612.68
  Bottom Layer w5: v1(206.55,1087.9) 211.05,1092.41 500.21,1092.41 746.36,846.25 746.36,828.64 v2(750,825)
DIR_TMS_SWDIO: U1.5 U15.14 | length 784.3
  Top Layer w6: U15.14@953.58,947.32 953.58,973.99 956.95,977.36 956.95,978.29 966.51,987.85 967.44,987.85 1086.13,1106.54 1381.8,1106.54 1479.4,1204.13 1479.4,1243.36 1460.78,1261.98 1443.79,1261.98 1428.52,1277.25 1428.52,1306.42 U1.5@1426.64,1308.31
DIR_TRST_RTS: U8.5 U15.2 | length 1100.7
  Top Layer w6: U8.5@267.26,1303.31 267.85,1302.72 267.85,1274.24 282.53,1259.56 308.14,1259.56 323.94,1243.76 323.94,1153.79 v2(348.06,1129.67) ; v2(801.52,851.68) 830.72,851.68 990.98,691.42 U15.2@1032.32,691.42
  Bottom Layer w5: v2(348.06,1129.67) 356.33,1121.41 553.59,1121.41 801.52,873.48 v2(801.52,851.68)
DIR_VCP_RX: U14.5 U15.22 | length 688.5
  Top Layer w6: U14.5@378.69,1303.31 380.07,1301.93 380.07,1277.14 396.6,1260.6 404.2,1260.6 430,1234.81 430,1140.06 444.61,1125.45 599.3,1125.45 622.05,1102.71 732.18,1102.71 776.38,1058.51 796.1,1038.79 U15.22@796.1,947.32
F_VDD: C26.2 R43.2 R44.2 U19.3 U19.7 U19.8 | length 753.2
  Bottom Layer w15: U19.3@1331.15,2022.48 1331.15,1976.4 1365.9,1941.66 1505.72,1941.66 ; U19.7@1381.15,2252.48 U19.8@1431.15,2252.48 1431.15,2220.68 1459.92,2191.92 C26.2@1490.07,2191.92 1491.66,2190.33 R44.2@1491.66,2129.84 1501.75,2129.84 1534.43,2097.15 1534.43,1970.37 1505.72,1941.66 ; 1501.1,1864.5 1501.1,1937.04 1505.72,1941.66
GND: C1.1 C2.1 C3.1 C4.1 C5.1 C6.1 C7.1 C8.1 C9.1 C10.1 C11.1 C12.1 C13.1 C14.1 C15.1 C16.1 C17.1 C18.1 C19.1 C20.1 C21.1 C22.1 C23.1 C24.1 C25.1 C26.1 C27.1 C28.1 C29.1 C30.1 C31.1 C32.1 C33.1 C34.1 CN1.5 CN2.4 CN3.15 CN5.3 JP3.3 K1.3 K1.4 K3.3 K3.4 LED_VDD*.2 PYLK.A1 PYLK.A12 PYLK.B1 PYLK.B12 Q1.2 R1.1 R3.2 R5.1 R8.2 R20.1 R21.1 R25.1 R28.2 R30.1 R33.2 R57.1 U1.2 U2.2 U3.2 U4.2 U5.2 U6.2 U7.2 U8.2 U9.1 U10.2 U11.2 U12.2 U13.2 U14.2 U15.8 U15.23 U15.47 U16.2 U17.4 U18.15 U19.4 U20.2 U21.2 Y1.2 Y1.4 Y2.2 Y2.4 | length 7512
  Top Layer w6: U18.15@1002.6,2478.94 1002.6,2429.4 1019,2413 1506.05,2413 1540.23,2447.19 1656.35,2447.19 1699.59,2490.43 CN3.15@1699.59,2494.77 ; U21.2@1310.5,3797.8 1310.5,3822.5 v2(1311,3823) ; v2(1495,1265) 1525,1265 1538.06,1251.94 U5.2@1538.06,1221.69
  Top Layer w10: U7.2@153.55,1216.69 U7.2@154.27,1215.97 ; R30.1@195,535 200,540 v2(200,570) ; C16.1@210,210 210,200 C16.1@215,195 ; v2(255,1164.6) 265.89,1175.49 265.89,1215.32 U8.2@267.26,1216.69 ; C2.1@265,375 C2.1@270,380 ; C3.1@335,336 C3.1@336,335 ; R8.2@365,535 v2@453.95,535 ; v2(372.9,1155.7) 378.59,1161.39 U14.2@378.59,1216.59 ; R20.1@401.52,735.88 R20.1@403.04,737.4 ; v2(453.1,534.15) v2@453.95,535 ; U20.2@460,3804.3 v2(460,3834.3) ; R3.2@480,535 v2@453.95,535 ; U12.2@490.12,1216.69 491.41,1215.4 491.41,1172.62 501.83,1162.2 501.83,1156.83 v2@500,1155 ; C21.1@593.36,1020 603.36,1030 C21.1@604,1030 597.95,1036.05 597.95,1054.14 619.23,1075.42 721.98,1075.42 756.82,1040.58 ; C17.1@628.59,509.5 C17.1@629.59,510.5 ; PYLK.A1@743.31,309.89 PYLK.B12@755.12,309.89 ; PYLK.B1@995.28,309.89 PYLK.A12@1007.09,309.89 ; v2@1039.47,613.56 v2@1039.6,613.69 ; v2@1041.61,614.02 1059.36,614.02 1088.57,584.8 1137.07,584.8 1154.91,566.95 C20.1@1154.87,537.59 ; U2.2@1314.26,1220.75 1317.1,1223.58 1317.1,1242.95 1334.15,1260 v2@1370.02,1260 ; v2(1369.2,1257.6) 1370.02,1258.42 v2@1370.02,1260 ; U1.2@1426.64,1221.69 1424.75,1223.58 1424.75,1245.25 1410,1260 v2@1370.02,1260 ; U10.2@1649.49,1221.69 1651.38,1219.8 1651.38,1193.96 1663.61,1181.72 1715,1181.72
  Top Layer w11: 178.68,1490.47 178.68,1583.91 199.86,1605.09 ; 756.82,1040.58 776.42,1020.98 U15.23@776.42,947.32 ; U15.47@953.58,612.68 953.58,655.91 959.74,662.07 982.08,662.07 1027.87,616.28 v2(1039.35,616.28) ; U15.8@1032.32,809.53 1199.94,809.53 1221.47,788 C22.1@1225.12,788
  Top Layer w12: Q1.2@50.2,1009.8 Q1.2@55.01,1004.99 ; v2(1561.71,954.27) 1566.84,954.27 1555,966.11 1555,1088.88 1579.39,1113.27 v2(1579.39,1113.51) ; v2(1645,520) 1688,477 C6.1@1688,449 ; C18.1@1711,1150 1715,1154 1715,1181.72 v2(1715,1200)
  Top Layer w15: U16.2@149.48,304.48 150.91,303.04 150.91,269.09 C16.1@210,210 ; C16.1@215,195 v2(272.56,195) ; U6.2@470.66,310.05 472.24,308.47 473.29,309.52 v2(498.08,309.52) ; v2(1210,150) U13.2@1260,150 1262.16,152.16 1294.66,152.16 1308.23,165.74 v2@1354.26,165.74 ; v2(1215,295) R25.1@1260,295 ; C34.1@1237,3669 1297,3669 v2(1322,3644) ; v2(1355,165) 1355,209.44 1366.26,220.7 K1.4@1376.55,220.7 v2(1376.55,285) ; K3.3@1393,3604 1393.5,3604.5 1474.5,3604.5 v2(1475,3605) ; v2(1615,3600) 1616.72,3601.72 1688.72,3601.72 K3.4@1691,3604 ; v2@1639.84,284.84 1639.84,241.67 1640.36,241.15 1640.36,231.96 1651.61,220.7 K1.3@1674.55,220.7
  Top Layer w20: C16.1@210,210 v2(210,245) ; C2.1@270,380 v2(310,380) ; v2(309.83,832.29) 310.59,833.04 341.17,833.04 R21.1@341.93,833.8 ; C3.1@336,335 v2(365,335) ; R20.1@403.04,737.4 403.04,737.12 407.52,732.64 429.94,732.64 v2(430.7,731.87) ; v3(712.08,365) 715.03,365 PYLK.A1@749.17,330.85 ; v2@790,3600 814,3624 LED_VDD*.2@814,3653 ; CN1.5@915,1380 CN1.5@922.47,1387.47 ; CN5.3@920,1645 CN5.3@924.36,1640.64 ; PYLK.A12@1002.26,328.72 v3(1023.55,350) ; C22.1@1220.12,797 1225.12,792 C22.1@1225.12,788 1225.41,788.28 1258.41,788.28 1270.12,800 v2(1270.12,867.57) 1293.95,891.41 1370.41,891.41 v2(1376.26,885.55) 1377.35,885.55 1380.45,888.65 1436.47,888.65 v2(1447.03,878.1) 1457.58,867.54 v2(1457.58,803.85) 1457.58,740.13 1457.58,592.46 v2(1435.12,570) 1419.85,554.73 1349.89,554.73 v2@1339.64,564.98 ; v2(1273.98,682.29) 1301.06,682.29 Y1.2@1316.66,666.69 1318.39,664.96 1318.39,591.73 C19.1@1320.12,590 1324.12,590 1329.12,585 1329.12,575.5 1330.37,574.25 ; 1330.37,570.63 v2(1337.83,563.18) ; C25.1@1382.12,840 1382.85,839.27 1382.85,754.04 Y1.4@1383.59,753.31 1396.74,740.16 v2(1457.55,740.16)
  Top Layer w25: v1(609.72,2137.68) 604.9,2132.87 v1(604.9,1998.57) v1(630.59,1972.88) C32.1@664.8,1972.88 665.81,1971.87 C33.1@767.97,1971.87 790.57,1971.87 v1(818.5,1999.8) 818.5,2128.72 v1(817.31,2129.92) ; Y2.2@949.56,2085.41 v1(913.12,2085.41) v1(889.83,2062.12) v1(889.83,2021.66) v1(889.83,1981.2) 897.41,1973.62 v1(913.36,1957.68) v1(913.36,1924.08) v1(931.59,1905.84) 1036.18,1905.84 ; v1(992.86,1905.84) 1036.18,1905.84 ; C29.1@1025.4,1953.04 1073.45,1953.04 v1@1079.9,1959.49 ; 1036.18,1912.77 Y2.4@1036.18,2018.48 C29.1@1036.18,1953.04 ; Y2.4@1036.18,2013.99 v1(1085.29,1964.88) v1@1079.9,1959.49 ; v1@1090.68,1970.27 1113.83,1970.27 v1(1146.17,1970.27) v1(1167.62,1991.72) 1167.62,2016.37 v1(1167.62,2037.25) v1(1167.62,2079.62) 1167.62,2095.87 v1(1152.77,2110.72) v1(1137.92,2125.57) ; v1(1113.83,1974.86) C30.1@1113.83,2016.37 1165.73,2016.37 ; 1036.18,1905.84 v1(1054.12,1905.84) v1(1079.9,1931.62) v1@1079.9,1959.49
  Bottom Layer w6: v2@499.26,1157.83 v2(502.89,1157.83)
  Bottom Layer w10: v2(502.89,1157.83) 502.89,1239.49 572.46,1309.06 615.72,1309.06 638,1286.78 638,1215.79 665.89,1187.9 v2(665.89,1185.89) ; v2@665,1183 683.72,1164.28 750.81,1164.28 U3.2@751.54,1165
  Bottom Layer w20: CN1.5@915,1380 921,1386 921,1642.94 CN5.3@918.94,1645
  other v1: 500.23,72.73 574.48,72.72 602,481 1223.05,527.77 622.75,533.15 239.93,578.18 704.43,621.59 833.63,683.94 768.47,684.5 445.71,923.68 1531.33,954.53 1597.76,958.38 464.86,967.62 863.55,1001.58 1313.59,1033.06 1368.58,1033.45 1256.66,1033.84 1421.24,1034.63 1530.67,1035.55 284,1062 195,1139 1235.29,1180.47 1227.19,1218.9 1711.69,1229.78 1713.32,1260.65 1186.59,1411.54 88.6,1424 29.3,1434.1 969,1480 882,1481 921,1481 550,1625 100,1675 1250,1675 580,1686 475,1700 345,1711 1129.65,1714.92 1248,1721.25 538.39,1721.93 325,1750 506.11,1756.93 379,1772 573.07,1805.76 325,1825 400,1825 514,1870 325,1900 1274,1914 1331.55,1923.29 1150,1925 1200,1950 1299.65,1950.35 694.59,1971.36 732.55,1972.48 818.5,2064.26 604.9,2065.72 1281,2124 1360.3,2129.34 1417.93,2163.54 1200.45,2203.26 1199,2251 1208,2415 1492,2447 1410,2450 1408.83,2520.13 1524.38,2520.42 1206,2526 1485,2527 1037.39,2607.91 758,2647 1036.68,2676.9 775.12,2686.84 1036.12,2726.67 960.84,2735 793.12,2739.73 1036.47,2803.11 900,2825 919.16,2850 529.01,2879.32 556.77,2920.96 657.61,2955.19 1103.95,2965.79 1200,3000 1100,3050 1300,3050 1200,3150 1450,3150 1100,3200 1200,3250 631,3282 510,3288 577,3298 1100,3300 300,3350 500,3350 600,3350 1350,3350 1450,3350 200,3400 50,3450 150,3450 250,3450 450,3450 700,3450 1300,3450 1400,3450 1550,3450 1700,3450 753,3486 900,3500 1150,3500 1700,3500 1100,3550 1300,3550 100,3700 200,3700 300,3700 400,3700 1350,3700 1450,3700 1550,3700 1700,3700
  other v2: 765,70 867.5,70 970,70 1100,70 1462.25,73 1520,73 1730,80 1095,95 1730,140 1510,150 1560,150 775,165 865,165 970,165 1680,195 1480,285 1560,285 1640,285 1737,298 150,355 1737,500 1635,575 1635,640 165,650 210,650 1460.12,660 57.3,975.34 60,1035 1182.35,1167.57 1241.94,1264.95 35,1375 1285,1480 1380,1480 1495,1480 1730,1480 35,1485 143,1490 1205,1650 552.55,3446 502.12,3597.36 788,3598 1050,3696 779,3795 903,3797 1004,3800 1099.32,3800.93
L_USB_CN_DM: PYLK.A7 PYLK.B7 U6.4 | length 509.3
  Top Layer w6: U6.4@568.15,272.6 569.18,271.57 569.18,254.46 596.04,227.6 816.36,227.6 845.49,256.73 PYLK.B7@845.49,309.71 ; PYLK.B7@845.67,309.89 845.67,355.67 855,365 875,365 885.04,354.96 PYLK.A7@885.04,309.89
L_USB_CN_DP: PYLK.A6 PYLK.B6 U6.6 | length 675
  Top Layer w6: U6.6@568.15,347.4 567.26,346.51 540.39,346.51 530.35,336.47 530.35,240.4 563.22,207.53 822.27,207.53 862.55,247.81 863.85,249.11 864.95,250.21 ; 865.75,246.61 865.75,244.61 866.31,244.04 870.05,240.31 899.06,240.31 904.31,245.56 PYLK.B6@904.31,309.48 ; 865.75,247.21 PYLK.A6@865.75,309.5
LED_BLUE: R9.2 U15.28 | length 675.2
  Top Layer w6: R9.2@220,710 225.04,710 303.26,631.77 438.53,631.77 521.33,714.58 521.33,827.41 543.92,850 575,850 595.79,829.21 U15.28@697.68,829.21
LED_GREEN: R6.2 U15.26 | length 724.3
  Top Layer w6: R6.2@220,820 291.82,748.18 291.82,725.67 335.36,682.13 432.27,682.13 483.48,733.34 483.48,848.48 541.75,906.75 591.91,906.75 630.07,868.58 U15.26@697.68,868.58
LED_RED: R4.2 U15.27 | length 692.2
  Top Layer w6: R4.2@220,765 224.07,765 335.03,654.04 432.13,654.04 502.68,724.59 502.68,837.68 540,875 590,875 616.1,848.9 U15.27@697.68,848.9
NetC1_2: C1.2 PYLK.1 PYLK.2 PYLK.3 PYLK.4 R8.1 | length 1440.4
  Top Layer w8: R8.1@365,475 368.29,471.71 368.29,443.87 424.64,387.52 611.97,387.52 705.12,294.37 PYLK.1@705.12,284.29 ; PYLK.3@705.12,119.73 PYLK.4@1045.28,119.73 PYLK.2@1045.28,284.29
  Bottom Layer w8: PYLK.3@705.12,119.73 849.27,119.73 C1.2@850,119 ; PYLK.1@716.04,295.21 PYLK.2@1034.36,295.21
  Bottom Layer w20: PYLK.1@705.12,284.29 PYLK.1@716.04,295.21 ; PYLK.2@1034.36,295.21 PYLK.2@1045.28,284.29
NetC17_2: C17.2 R31.2 | length 64.1
  Top Layer w6: 686.21,571.75 686.21,513.88 C17.2@690.59,509.5
NetC29_2: C29.2 R54.1 Y2.3 | length 238.9
  Top Layer w6: C29.2@963.4,1953.04 949.56,1966.88 Y2.3@949.56,2018.48 957.32,2018.48 992.53,2053.7 992.53,2154.59 985.95,2161.17
NetC30_2: C30.2 R56.1 Y2.1 | length 158.7
  Top Layer w6: 1037.04,2163.18 1037.04,2086.28 Y2.1@1036.18,2085.41 1043.22,2078.37 C30.2@1113.83,2078.37
NetC31_2: C31.2 K2.3 K2.4 R55.1 R57.2 U20.1 | length 1019.3
  Top Layer w6: K2.4@86,3780 K2.3@384,3780 384.15,3779.85 459.85,3779.85 U20.1@460,3779.7 460,3777.83 480,3757.83 C31.2@480,3725 485,3720 R57.2@538,3720 v2(619,3720)
  Bottom Layer w6: v2@621.62,3722.62 v2(619,3720) 619,3436.75 R55.1@728,3327.75
NetC32_2: C32.2 R58.1 Y3.2 | length 176.8
  Top Layer w6: C32.2@664.8,2034.88 666.7,2036.77 666.7,2090.64 666.7,2123 692.33,2148.63 692.33,2182.17 ; Y3.2@666.7,2093.5 Y3.2@666.7,2111.6
NetC33_2: C33.2 R61.1 Y3.1 | length 159.6
  Top Layer w6: 742.01,2182.69 742.01,2149.95 767.09,2124.88 Y3.1@767.09,2111.6 767.09,2034.75 C33.2@767.97,2033.87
